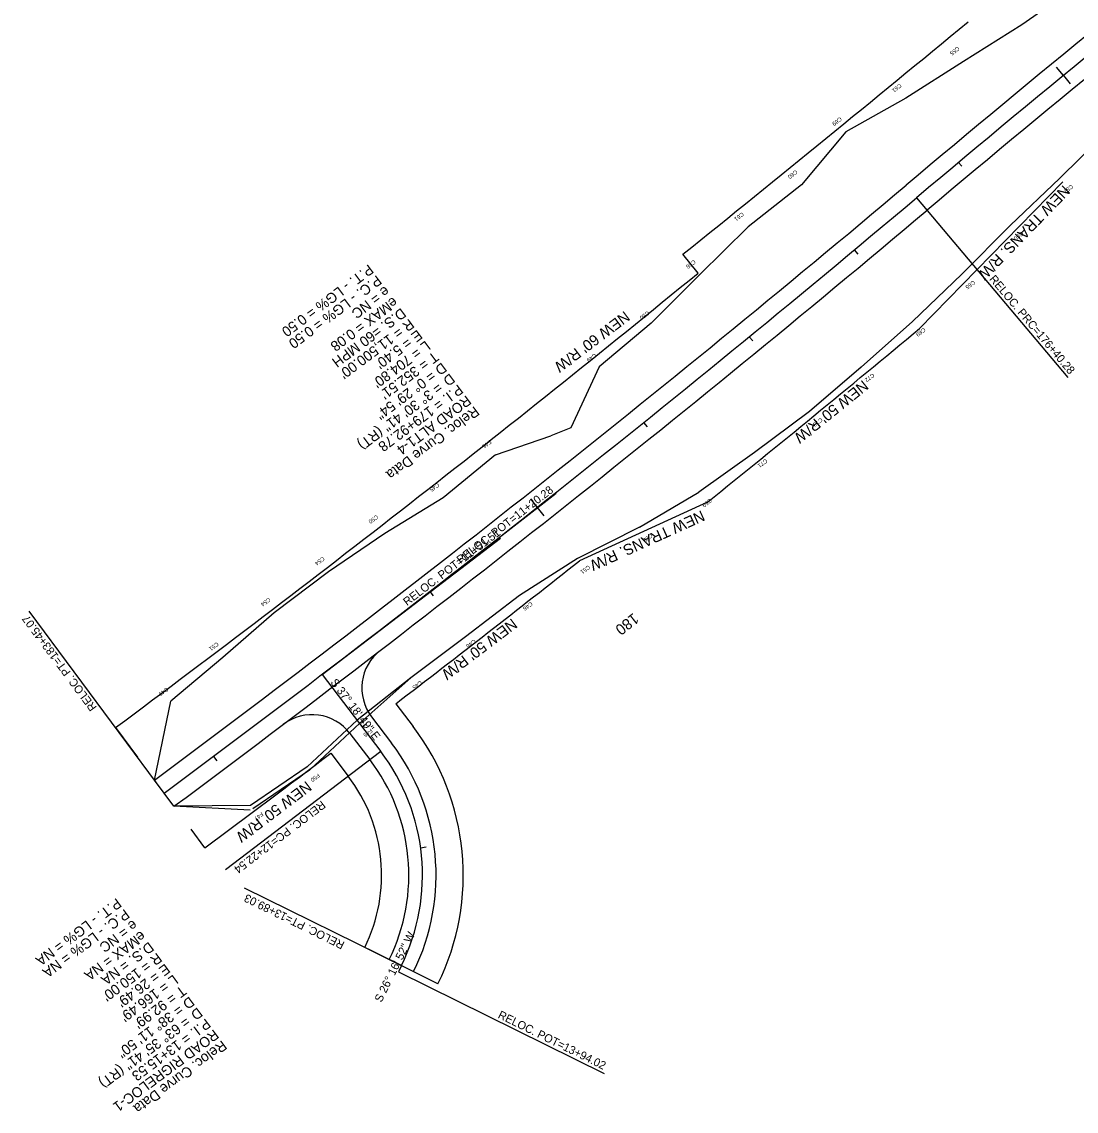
# Model space of a CAD drawing. Extents: x 1469024 to 1473560, y 1105695 to 1109739.
# Drawn here: x 1469878 to 1470653, y 1106567 to 1107367 of the extents above; entities that cross this region are included whole.
import ezdxf

# ---------------------------------------------------------------- set-up
doc = ezdxf.new("R2010")
doc.units = 0
for name, color, linetype in [('RD_HC_CL_Rel', 7, 'Continuous'), ('RD_HC_Data_Rel', 7, 'Continuous'), ('RD_HC_Data_Tic_Rel', 7, 'Continuous'), ('RD_HC_TX_Rel_Sta50', 7, 'Continuous'), ('RD_PD_CstnLmt', 7, 'Continuous'), ('RD_PD_CstnLmt_TX', 7, 'Continuous'), ('RD_PD_DR_ErosCtrl', 7, 'Continuous'), ('RD_PD_Final_TrvlWay', 7, 'Continuous'), ('RD_PD_RW', 7, 'Continuous'), ('RD_PD_RW_TX', 7, 'Continuous')]:
    doc.layers.add(name, color=color, linetype=linetype)

msp = doc.modelspace()

# ---------------------------------------------------------------- linework, layer by layer
at = {"layer": 'RD_HC_CL_Rel'}
for p, q in [((1470099.05, 1106887.38), (1470142.11, 1106830.89)), ((1470157.3, 1106673.55), (1470155.09, 1106669.07))]:
    msp.add_line(p, q, dxfattribs=at)
for centre, radius, start, end in [((1477943.58, 1098441.09), 11500, 126.41418, 130.102414), ((1463127.99, 1116033.66), 11500, 306.590952, 310.102414), ((1470022.81, 1106739.97), 150, 333.71897, 37.31373)]:
    msp.add_arc(centre, radius, start, end, dxfattribs=at)
at = {"layer": 'RD_HC_Data_Rel'}
for p, q in [((1470535.78, 1107237.37), (1470646.99, 1107105.32)), ((1470138.82, 1106917.69), (1470271.1, 1107020.34)), ((1470099.05, 1106887.38), (1470230.24, 1106987.37)), ((1469983.12, 1106800.17), (1469883.84, 1106933.9)), ((1470142.11, 1106830.89), (1470028.08, 1106743.99)), ((1470157.3, 1106673.55), (1470042.13, 1106730.43)), ((1470155.09, 1106669.07), (1470306.17, 1106594.47))]:
    msp.add_line(p, q, dxfattribs=at)
at = {"layer": 'RD_HC_Data_Tic_Rel'}
for p, q in [((1470643.63, 1107327.08), (1470638.55, 1107333.26)), ((1470643.63, 1107327.08), (1470648.71, 1107320.89)), ((1470566.42, 1107263.53), (1470568.96, 1107260.43)), ((1470490, 1107199.02), (1470492.56, 1107195.95)), ((1470412.9, 1107135.34), (1470415.44, 1107132.24)), ((1470335.25, 1107072.33), (1470337.76, 1107069.21)), ((1470252.1, 1107016.27), (1470257.05, 1107010)), ((1470257.05, 1107010), (1470262.01, 1107003.72)), ((1470178.32, 1106948.35), (1470180.77, 1106945.19)), ((1470099.05, 1106887.38), (1470101.48, 1106884.2)), ((1470128.44, 1106848.82), (1470131.63, 1106851.24)), ((1470019.26, 1106827.11), (1470021.65, 1106823.91)), ((1470171.44, 1106760.13), (1470175.41, 1106760.67))]:
    msp.add_line(p, q, dxfattribs=at)
at = {"layer": 'RD_PD_CstnLmt'}
for p, q in [((1470654.32, 1107393.13), (1470613.1, 1107364.23)), ((1470613.1, 1107364.23), (1470570.26, 1107337.48)), ((1470570.26, 1107337.48), (1470527.96, 1107310.43)), ((1470527.96, 1107310.43), (1470483.78, 1107285.7)), ((1470483.78, 1107285.7), (1470451.19, 1107246.79)), ((1470676.63, 1107286.9), (1470641.02, 1107251.62)), ((1470451.19, 1107246.79), (1470412.02, 1107215.93)), ((1470641.02, 1107251.62), (1470604.5, 1107217.08)), ((1470412.02, 1107215.93), (1470376.32, 1107180.78)), ((1470604.5, 1107217.08), (1470569.06, 1107181.21)), ((1470376.32, 1107180.78), (1470340.77, 1107145.39)), ((1470569.06, 1107181.21), (1470532.68, 1107146.44)), ((1470340.77, 1107145.39), (1470302.55, 1107113.31)), ((1470532.68, 1107146.44), (1470495.14, 1107113.08)), ((1470302.55, 1107113.31), (1470281.89, 1107068.44)), ((1470495.14, 1107113.08), (1470457.05, 1107080.39)), ((1470457.05, 1107080.39), (1470416.76, 1107050.43)), ((1470226.43, 1107048.72), (1470267.1, 1107062.64)), ((1470281.89, 1107068.44), (1470267.1, 1107062.64)), ((1470226.43, 1107048.72), (1470187.94, 1107016.95)), ((1470416.76, 1107050.43), (1470375.84, 1107021.28)), ((1470187.94, 1107016.95), (1470145.09, 1106990.76)), ((1470332.27, 1106995.5), (1470375.84, 1107021.28)), ((1470145.09, 1106990.76), (1470103.67, 1106962.77)), ((1470332.27, 1106995.5), (1470286.6, 1106972.42)), ((1470286.6, 1106972.42), (1470244.13, 1106945.35)), ((1470103.67, 1106962.77), (1470063.89, 1106932.69)), ((1470244.13, 1106945.35), (1470204.3, 1106914.94)), ((1470063.89, 1106932.69), (1470026.19, 1106899.9)), ((1470204.3, 1106914.94), (1470164.16, 1106884.93)), ((1470026.19, 1106899.9), (1469987.92, 1106867.84)), ((1470164.16, 1106884.93), (1470124.88, 1106853.82)), ((1469975.97, 1106809.81), (1469987.92, 1106867.84)), ((1470124.88, 1106853.82), (1470088.05, 1106819.52)), ((1470088.05, 1106819.52), (1470046.6, 1106791.21)), ((1470046.6, 1106791.21), (1469990.27, 1106790.54))]:
    msp.add_line(p, q, dxfattribs=at)
at = {"layer": 'RD_PD_DR_ErosCtrl'}
for p, q in [((1470164.16, 1106884.93), (1470126.74, 1106851.47)), ((1470126.92, 1106851.63), (1470090.09, 1106817.32)), ((1470089.74, 1106817.04), (1470048.29, 1106788.73)), ((1470046.32, 1106787.63), (1469990.27, 1106790.54))]:
    msp.add_line(p, q, dxfattribs=at)
at = {"layer": 'RD_PD_Final_TrvlWay'}
for p, q in [((1470135.44, 1106856.13), (1470150.06, 1106836.96)), ((1470119.54, 1106844.01), (1470134.15, 1106824.83)), ((1469990.27, 1106790.54), (1469975.97, 1106809.81))]:
    msp.add_line(p, q, dxfattribs=at)
for centre, radius, start, end in [((1477943.58, 1098441.09), 11512, 126.41418, 130.102414), ((1477943.58, 1098441.09), 11488, 126.41418, 130.102414), ((1463127.99, 1116033.66), 11488, 306.590952, 310.102414), ((1463127.99, 1116033.66), 11512, 306.590952, 310.102414), ((1470163.28, 1106877.35), 35, 127.53702, 217.31373), ((1470091.7, 1106822.79), 35, 37.31373, 127.09044), ((1470022.81, 1106739.97), 160, 333.71897, 37.31373), ((1470022.81, 1106739.97), 140, 333.71897, 37.31373)]:
    msp.add_arc(centre, radius, start, end, dxfattribs=at)
at = {"layer": 'RD_PD_RW'}
for p, q in [((1470643.12, 1107249.07), (1470538.02, 1107141.4)), ((1470375.27, 1107182.07), (1470364.16, 1107195.89)), ((1470382.25, 1107013.88), (1470288.05, 1106970.76)), ((1470153.2, 1106865.83), (1470165.96, 1106849.08)), ((1469947.35, 1106848.35), (1469963.45, 1106826.67)), ((1470105.48, 1106829.46), (1470118.25, 1106812.71)), ((1470012.92, 1106760.03), (1470002.79, 1106773.68)), ((1470184.2, 1106660.27), (1470130.4, 1106686.83))]:
    msp.add_line(p, q, dxfattribs=at)
for centre, radius, start, end in [((1457250.32, 1123501.8), 20925, 308.80758, 309.547337), ((1463127.99, 1116033.66), 11440, 306.590952, 309.309091), ((1463127.99, 1116033.66), 11575, 308.808406, 309.804854), ((1463127.99, 1116033.66), 11550, 307.462554, 308.310182), ((1470022.81, 1106739.97), 180, 333.71897, 37.31373), ((1463127.99, 1116033.66), 11550, 306.590952, 307.164913), ((1470022.81, 1106739.97), 120, 333.71897, 37.31373)]:
    msp.add_arc(centre, radius, start, end, dxfattribs=at)

# ---------------------------------------------------------------- texts
at = {"layer": 'RD_HC_Data_Rel'}
for s, height, rotation, p in [('P.T. - LG% = 0.50', 7.5, 216.72833, (1470133.24, 1107188.89)), ('P.C. - LG% = 0.50', 7.5, 216.72833, (1470139.22, 1107180.87)), ('RELOC. PRC=176+40.28', 6, 310.10241, (1470588.85, 1107177.47)), ('e = NC', 7.5, 216.72833, (1470145.2, 1107172.86)), ('eMAX = 0.08', 7.5, 216.72833, (1470151.18, 1107164.84)), ('D.S. =60 MPH', 7.5, 216.72833, (1470157.16, 1107156.83)), ("R = 11,500.00'", 7.5, 216.72545, (1470163.14, 1107148.81)), ("E = 5.40'", 7.5, 216.72545, (1470169.12, 1107140.8)), ("L = 704.80'", 7.5, 216.72545, (1470175.1, 1107132.78)), ("T = 352.51'", 7.5, 216.72545, (1470181.08, 1107124.77)), ('D = 0%%d 29\' 54"', 7.5, 216.72545, (1470187.06, 1107116.75)), ('D', 7.5, 216.72545, (1470193.04, 1107108.74)), ('    = 3%%d 30\' 41" (RT)', 7.5, 216.72545, (1470193.04, 1107108.74)), ('P.I. = 179+92.78', 7.5, 216.72545, (1470199.02, 1107100.72)), ('ROAD ALT1-4', 7.5, 216.72833, (1470205, 1107092.71)), ('Reloc. Curve Data', 7.5, 216.72833, (1470210.98, 1107084.69)), ('RELOC. POT=11+20.28', 6, 37.81196, (1470200.79, 1106968.32)), ('RELOC. POT=11+51.51', 6, 37.31373, (1470161.46, 1106937.47)), ('RELOC. PT=183+45.07', 6, 126.59095, (1469933.83, 1106863.21)), ('S 37%%d 18\' 49" E', 6, 307.31373, (1470104.86, 1106881.41)), ('RELOC. PC=12+22.54', 6, 217.31373, (1470098.68, 1106794.98)), ('RELOC. PT=13+89.03', 6, 153.71897, (1470116.14, 1106690.65)), ('P.T. - LG% = NA', 7.5, 216.56161, (1469948.1, 1106723.53)), ('P.C. - LG% = NA', 7.5, 216.56161, (1469954.06, 1106715.5)), ('e = NC', 7.5, 216.56161, (1469960.01, 1106707.47)), ('eMAX = NA', 7.5, 216.56161, (1469965.97, 1106699.44)), ('S 26%%d 16\' 52" W', 6, 63.71897, (1470142.64, 1106646.12)), ('D.S. = NA', 7.5, 216.56161, (1469971.93, 1106691.41)), ("R = 150.00'", 7.5, 216.56161, (1469977.88, 1106683.37)), ("E = 26.49'", 7.5, 216.56161, (1469983.84, 1106675.34)), ("L = 166.49'", 7.5, 216.56161, (1469989.8, 1106667.31)), ("T = 92.99'", 7.5, 216.56161, (1469995.76, 1106659.28)), ('D = 38%%d 11\' 50"', 7.5, 216.56161, (1470001.71, 1106651.25)), ('D', 7.5, 216.56161, (1470007.67, 1106643.21)), ('RELOC. POT=13+94.02', 6, 333.71897, (1470227.71, 1106635.44)), ('    = 63%%d 35\' 41" (RT)', 7.5, 216.56161, (1470007.67, 1106643.21)), ('P.I. = 13+15.53', 7.5, 216.56161, (1470013.63, 1106635.18)), ('ROAD RIGRELOC-1', 7.5, 216.56161, (1470019.58, 1106627.15)), ('Reloc. Curve Data', 7.5, 216.56161, (1470025.54, 1106619.12))]:
    msp.add_text(s, height=height, rotation=rotation, dxfattribs=at).set_placement(p)
at = {"layer": 'RD_HC_TX_Rel_Sta50'}
msp.add_text('180', height=8, rotation=218.26191, dxfattribs=at).set_placement((1470327.73, 1106932.88))
at = {"layer": 'RD_PD_CstnLmt_TX'}
for s, rotation, p in [('C55', 217.81092, (1470565.87, 1107348.63)), ('C61', 217.6745, (1470523.37, 1107321.4)), ('C69', 217.53809, (1470479.44, 1107296.87)), ('C60', 217.40167, (1470446.87, 1107257.97)), ('C57', 217.81092, (1470649.32, 1107247.31)), ('C61', 217.26525, (1470407.51, 1107226.94)), ('C60', 217.6745, (1470612.82, 1107212.77)), ('C56', 217.12883, (1470372.06, 1107191.97)), ('C65', 217.53809, (1470577.36, 1107176.88)), ('C50', 216.99241, (1470338.15, 1107154.43)), ('C69', 217.40167, (1470540.97, 1107142.09)), ('C49', 216.99241, (1470299.22, 1107123.3)), ('C72', 217.26525, (1470503.4, 1107108.69)), ('C73', 217.12883, (1470465.33, 1107075.99)), ('F46', 216.58316, (1470222.09, 1107059.82)), ('C71', 216.99241, (1470424.8, 1107045.85)), ('C45', 216.44674, (1470183.82, 1107028.19)), ('C69', 216.99241, (1470384, 1107016.78)), ('C50', 216.31032, (1470138.96, 1107004.73)), ('C62', 216.99241, (1470340.38, 1106990.97)), ('C54', 216.1739, (1470099.59, 1106974.03)), ('C51', 216.58316, (1470294.61, 1106967.78)), ('C54', 216.03748, (1470059.84, 1106943.96)), ('C46', 216.44674, (1470252.35, 1106940.86)), ('C51', 215.90106, (1470021.74, 1106911.29)), ('C46', 216.31032, (1470210.65, 1106913.31)), ('C49', 215.76465, (1469984.74, 1106878.05)), ('C45', 216.1739, (1470171.19, 1106882.94)), ('F45', 216.03748, (1470134.78, 1106847.77)), ('F50', 215.90106, (1470096.04, 1106814.82)), ('F47', 215.76465, (1470054.56, 1106786.48))]:
    msp.add_text(s, height=3, rotation=rotation, dxfattribs=at).set_placement(p)
at = {"layer": 'RD_PD_RW_TX'}
for s, rotation, p in [('NEW TRANS. R/W', 225.88862, (1470643.49, 1107247.12)), ("NEW 60' R/W", 217.07932, (1470321.2, 1107154.6)), ("NEW 50' R/W", 218.77669, (1470496.24, 1107103.92)), ('NEW TRANS. R/W', 204.43098, (1470377.77, 1107008.07)), ("NEW 50' R/W", 217.07932, (1470238.49, 1106928.91)), ("NEW 50' R/W", 217.07932, (1470087.46, 1106809.52))]:
    msp.add_text(s, height=8, rotation=rotation, dxfattribs=at).set_placement(p)

doc.saveas('drawing.dxf')
